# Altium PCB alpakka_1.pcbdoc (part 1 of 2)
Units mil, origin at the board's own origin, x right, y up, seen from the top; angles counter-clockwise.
Board outline 6704.54 x 4318.9 mil, 4 copper layers (Top Layer, Inner1, Inner2, Bottom Layer); 97 components, 87 nets, 400 pads, 319 vias.
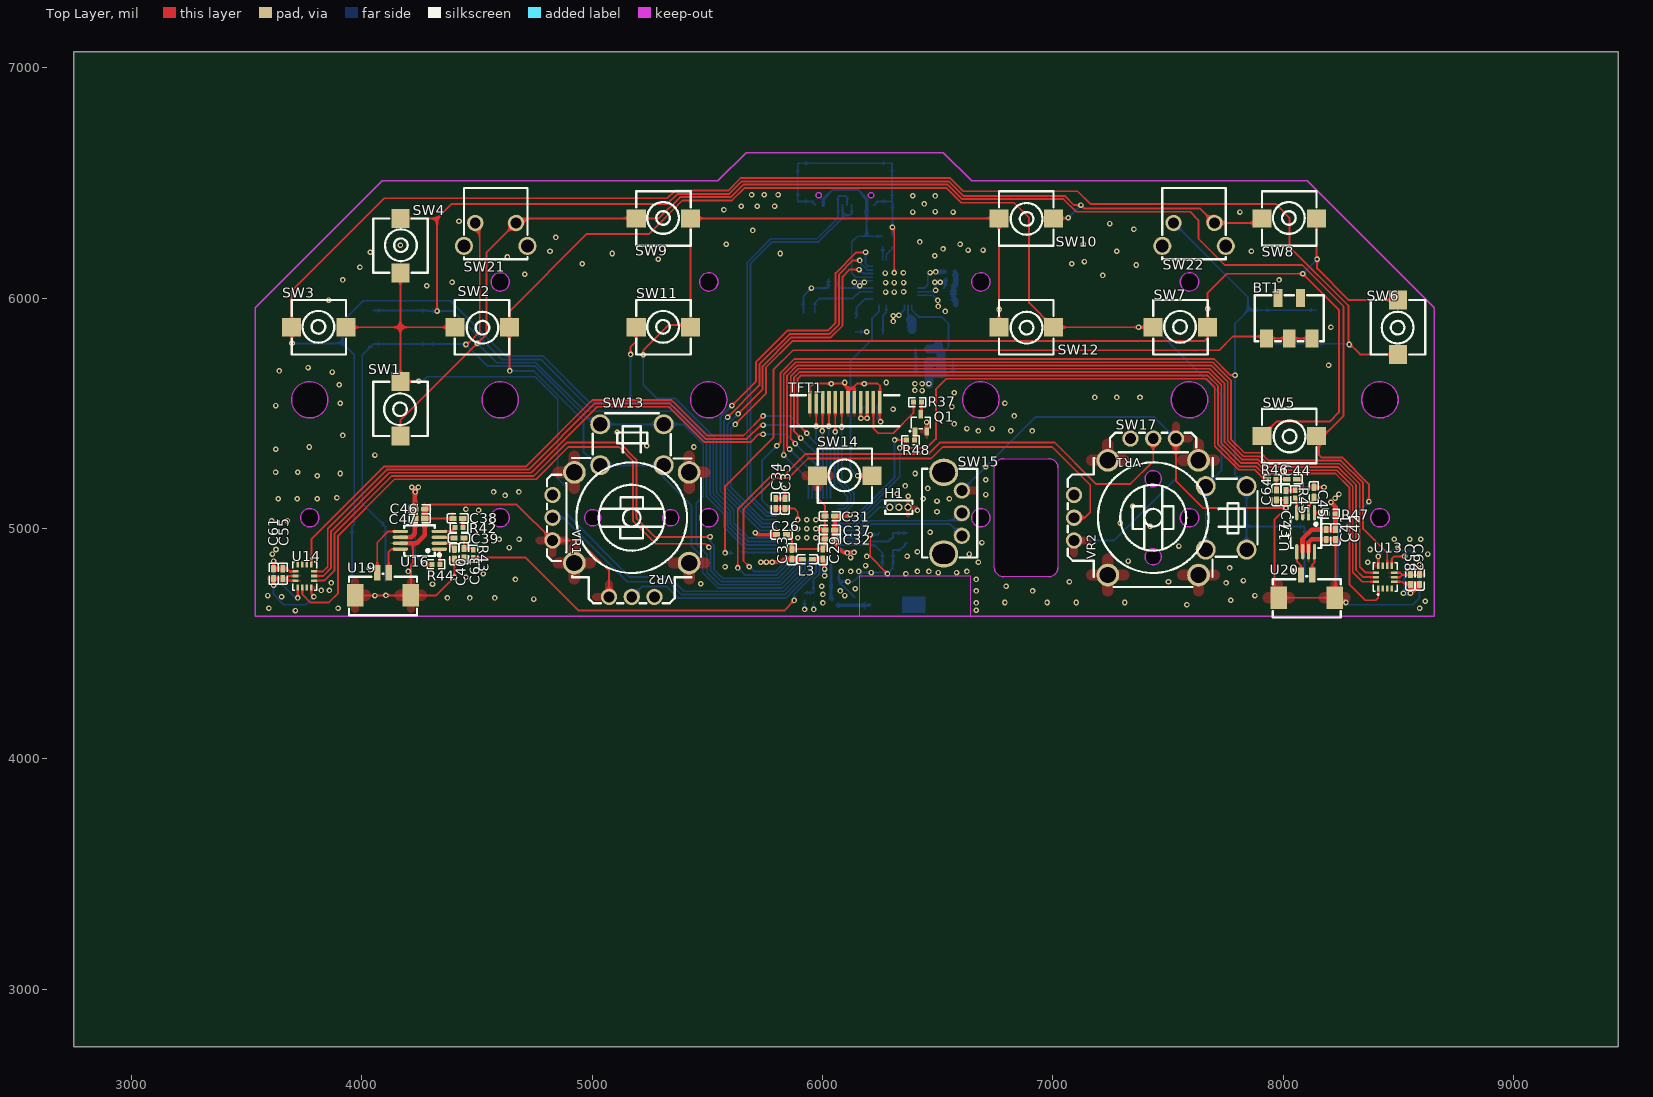
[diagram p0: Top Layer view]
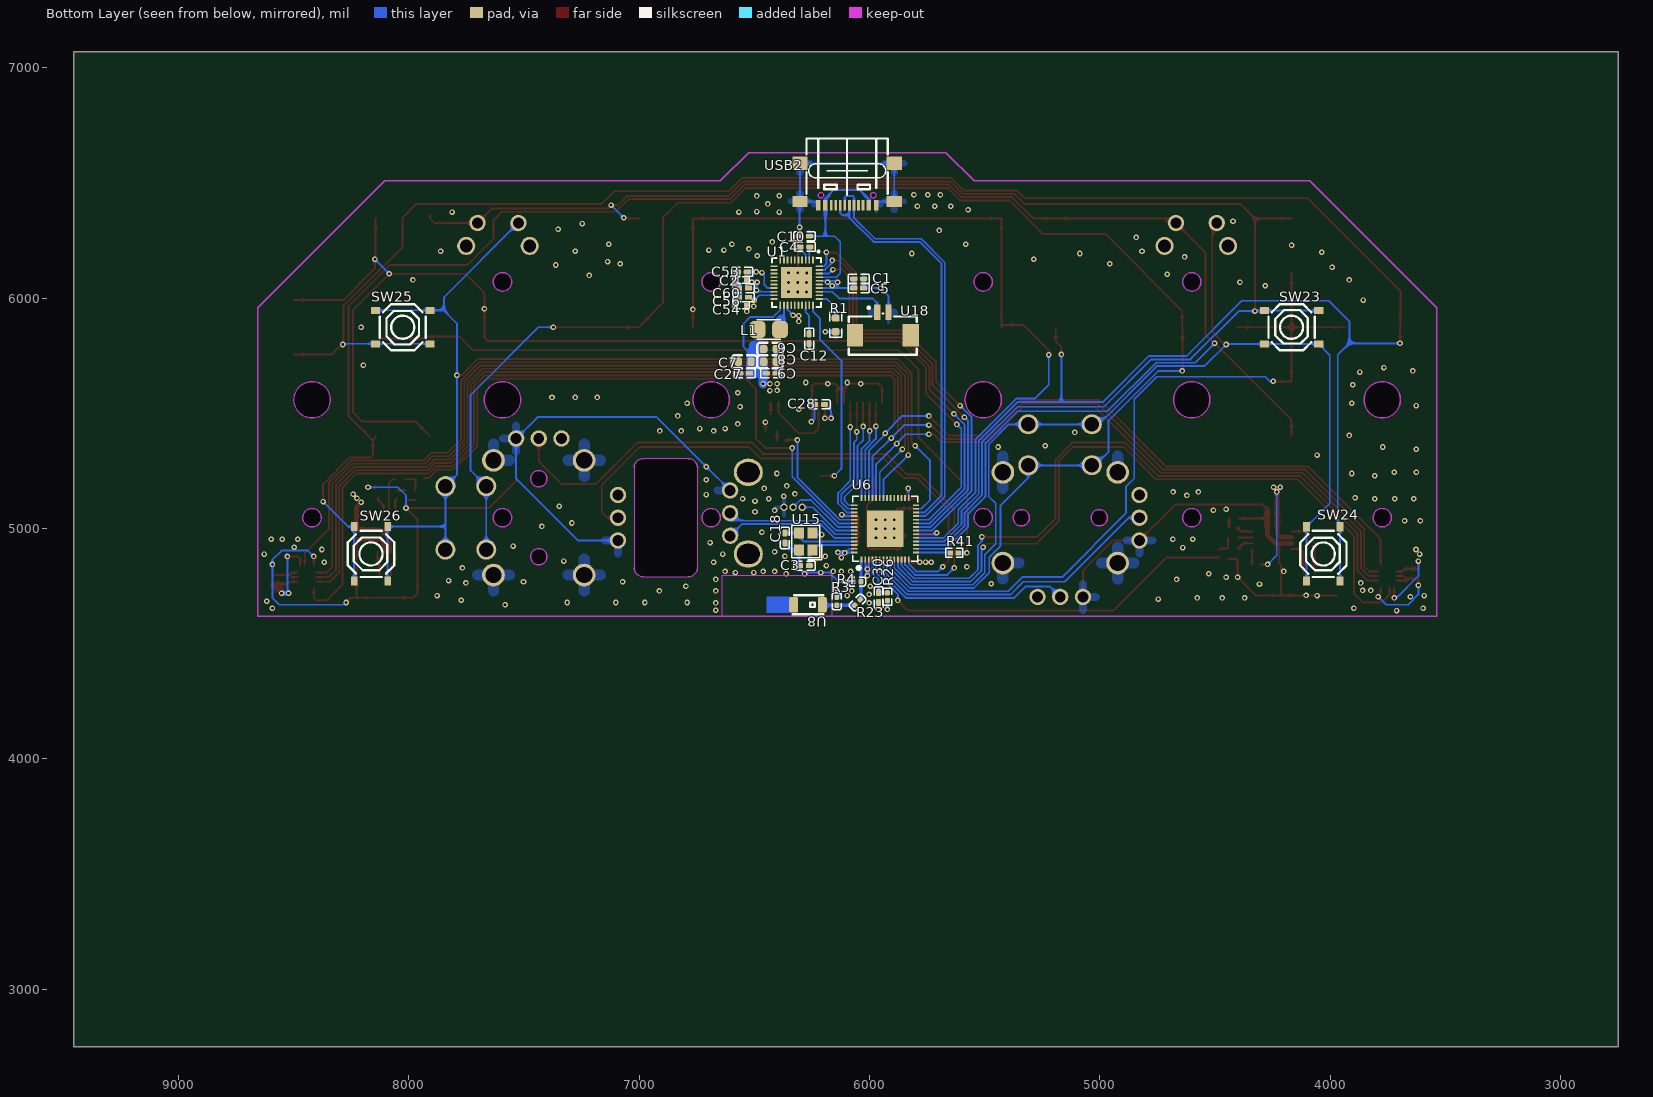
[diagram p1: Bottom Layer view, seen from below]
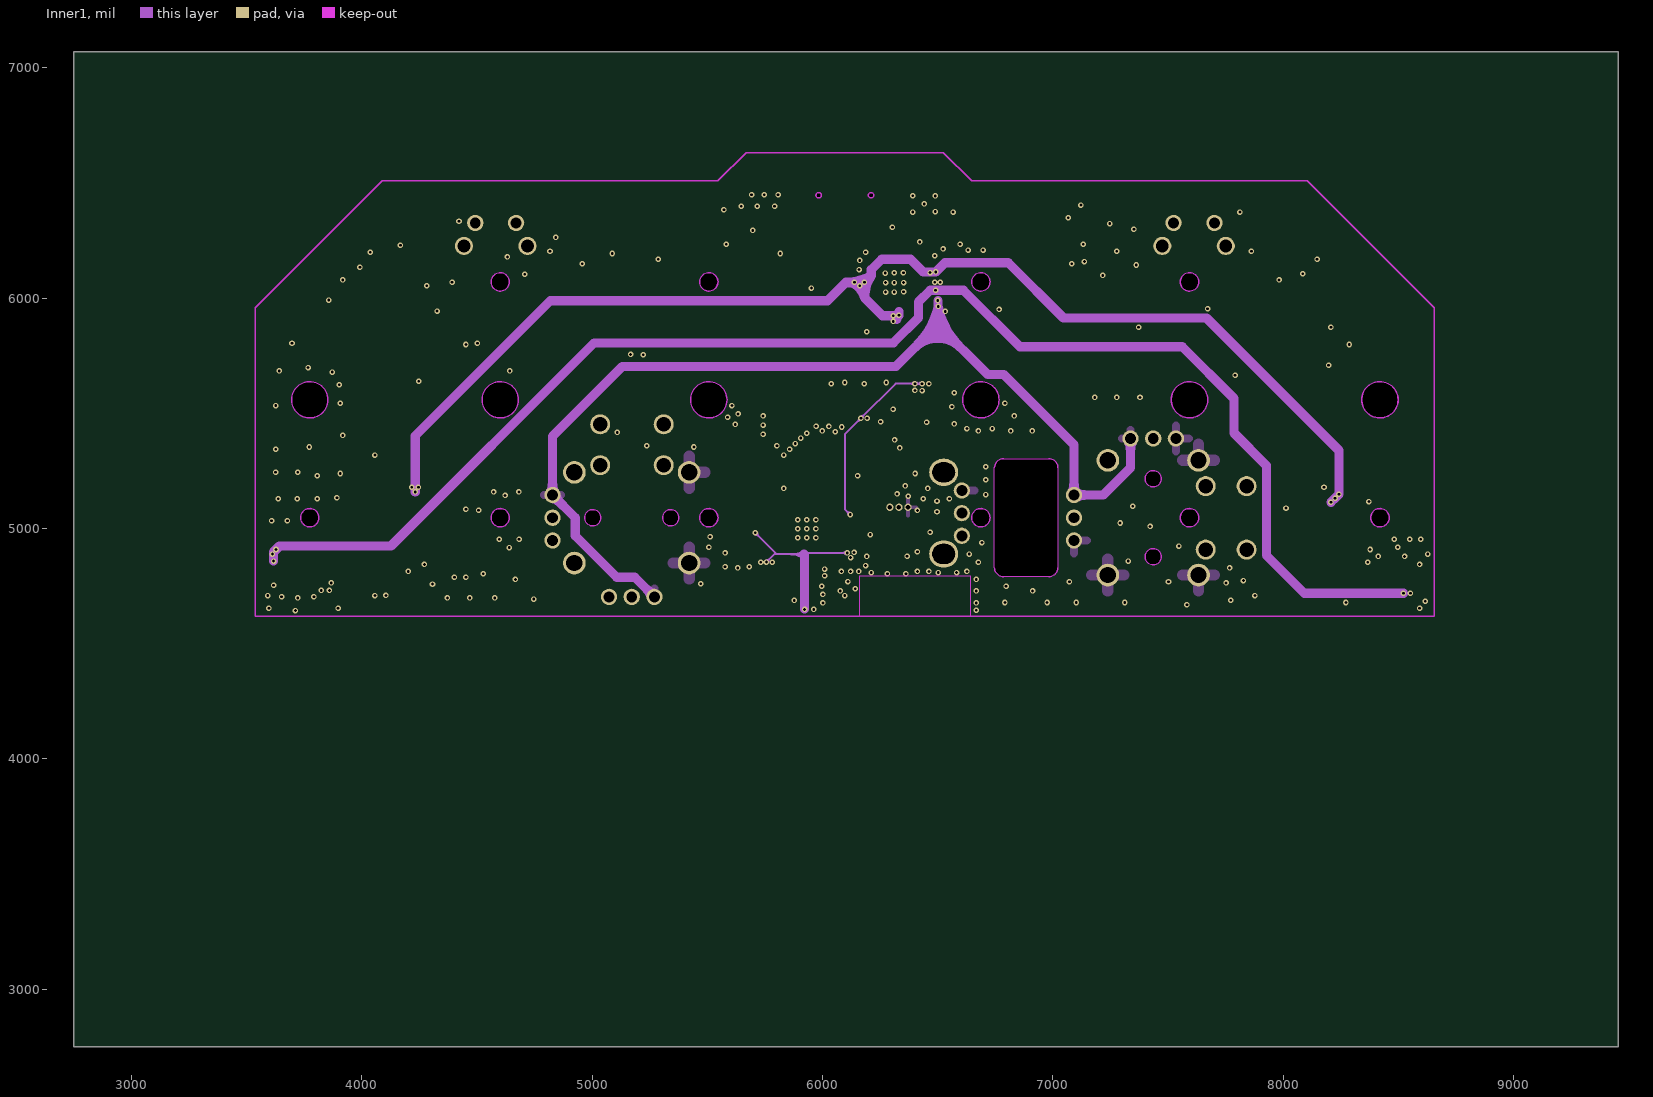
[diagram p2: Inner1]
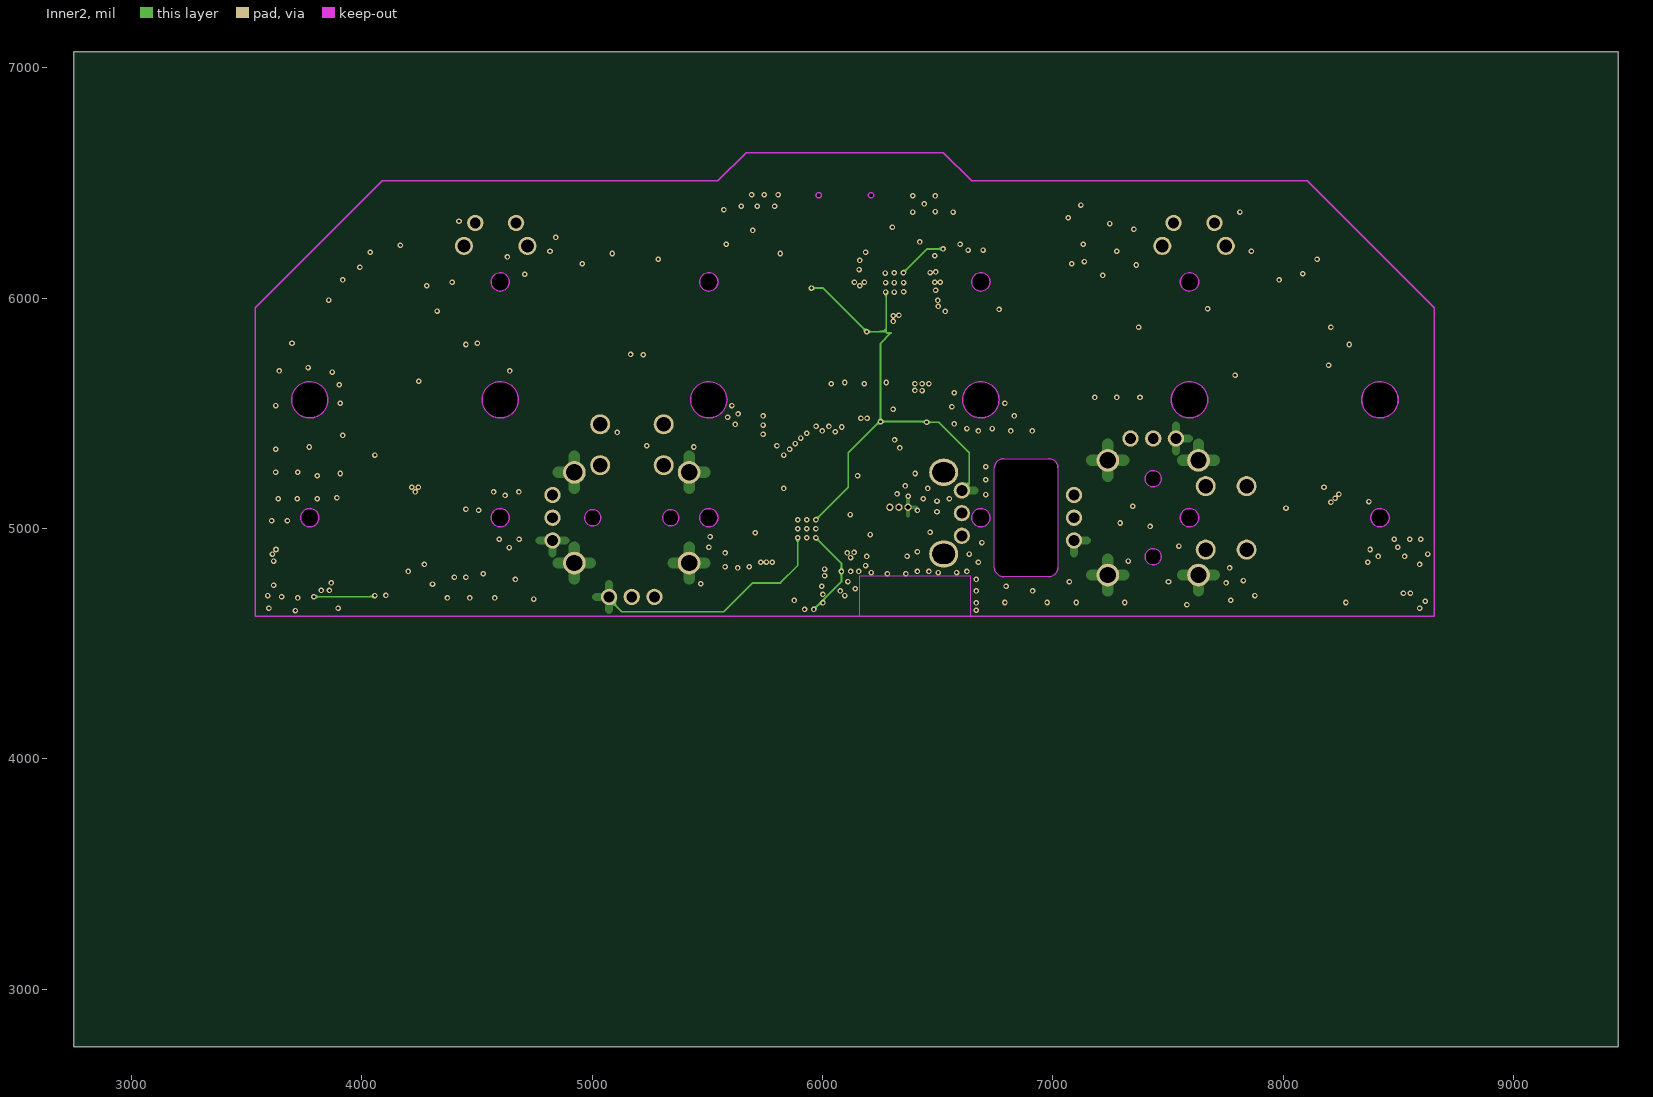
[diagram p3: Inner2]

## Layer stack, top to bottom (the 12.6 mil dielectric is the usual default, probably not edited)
Top Layer: signal copper (thickness not stored)
Dielectric: dielectric 12.6, FR-4, Dk 4.8
Inner1: signal copper (thickness not stored)
Dielectric: dielectric 12.6, FR-4, Dk 4.8
Inner2: signal copper (thickness not stored)
Dielectric: dielectric 12.6, FR-4, Dk 4.8
Bottom Layer: signal copper (thickness not stored)

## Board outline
9454.54,2750 2750,2750 2750,7068.9 9454.54,7068.9
cut-out: 3853.43,5558.11 cw(c3774.43,5558.11) 3695.43,5558.11 cw(c3774.43,5558.11)
cut-out: 3814.43,5046.3 cw(c3774.43,5046.3) 3734.43,5046.3 cw(c3774.43,5046.3)
cut-out: 4680.21,5558.11 cw(c4601.21,5558.11) 4522.21,5558.11 cw(c4601.21,5558.11)
cut-out: 5585.72,5558.11 cw(c5506.72,5558.11) 5427.72,5558.11 cw(c5506.72,5558.11)
cut-out: 6766.82,5558.11 cw(c6687.82,5558.11) 6608.82,5558.11 cw(c6687.82,5558.11)
cut-out: 7672.33,5558.11 cw(c7593.33,5558.11) 7514.33,5558.11 cw(c7593.33,5558.11)
cut-out: 8499.1,5558.11 cw(c8420.1,5558.11) 8341.1,5558.11 cw(c8420.1,5558.11)
cut-out: 4641.21,5046.3 cw(c4601.21,5046.3) 4561.21,5046.3 cw(c4601.21,5046.3)
cut-out: 4641.21,6069.92 cw(c4601.21,6069.92) 4561.21,6069.92 cw(c4601.21,6069.92)
cut-out: 5546.72,5046.3 cw(c5506.72,5046.3) 5466.72,5046.3 cw(c5506.72,5046.3)
cut-out: 5546.72,6069.92 cw(c5506.72,6069.92) 5466.72,6069.92 cw(c5506.72,6069.92)
cut-out: 6727.82,5046.3 cw(c6687.82,5046.3) 6647.82,5046.3 cw(c6687.82,5046.3)
cut-out: 6727.82,6069.92 cw(c6687.82,6069.92) 6647.82,6069.92 cw(c6687.82,6069.92)
cut-out: 8460.1,5046.3 cw(c8420.1,5046.3) 8380.1,5046.3 cw(c8420.1,5046.3)
cut-out: 7633.33,6069.92 cw(c7593.33,6069.92) 7553.33,6069.92 cw(c7593.33,6069.92)
cut-out: 7633.33,5046.3 cw(c7593.33,5046.3) 7553.33,5046.3 cw(c7593.33,5046.3)
cut-out: 6786.25,5302.14 6983.1,5302.27 cw(c6983.1,5262.91) 7022.47,5262.9 7022.47,4829.76 cw(c6982.82,4830.04) 6983.1,4790.39 6786.25,4790.39 cw(c6786.25,4829.76) 6746.88,4829.76 6746.88,5262.9 cw(c6786.25,5262.76)

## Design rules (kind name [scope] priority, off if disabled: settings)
BoardOutlineClearance safeClearance1 [All] p0: genericclearance=10 ignorepadtopadclearanceinfootprint=FALSE except(0: Arc-SplitContinuation Track-SplitContinuation SMDPad-SplitContinuation THPad-SplitContinuation Via-SplitContinuation Fill-SplitContinuation Poly-SplitContinuation Region-SplitContinuation Text-SplitContinuation; 6: Track-CutoutEdge SMDPad-CutoutEdge THPad-CutoutEdge Via-CutoutEdge Fill-CutoutEdge Region-CutoutEdge; 11.8: Track-OutlineEdge SMDPad-OutlineEdge THPad-OutlineEdge Via-OutlineEdge Fill-OutlineEdge Region-OutlineEdge Poly-OutlineEdge Text-OutlineEdge)
Clearance safeClearance1 [(InNet('GND') OR InNet('XTAL_P') OR InNet('XTAL_N') OR InNet('VDD3V3') OR InNet('$1N11781') OR InNet('ESP_EN') OR InNet('VDD_SPI') OR InNet('$1N13646') OR InNet('$1N13645') OR InNet('$1N11778') OR InNet('GPIO0') OR InNet('GPIO5') OR InNet('GPIO6') OR InNet('GPIO7') OR InNet('GPIO10') OR InNet('GPIO11') OR InNet('GPIO12') OR InNet('GPIO13') OR InNet('GPIO14') OR InNet('GPIO15') OR InNet('GPIO16') OR InNet('GPIO17') OR InNet('GPIO18') OR InNet('GPIO19') OR InNet('GPIO20') OR InNet('GPIO21') OR InNet('SPIHD') OR InNet('SPIWP') OR InNet('SPICS0') OR InNet('SPICLK') OR InNet('SPIQ') OR InNet('SPID') OR InNet('GPIO48') OR InNet('GPIO47') OR InNet('GPIO33') OR InNet('GPIO34') OR InNet('GPIO35') OR InNet('GPIO36') OR InNet('GPIO37') OR InNet('GPIO38') OR InNet('GPIO39') OR InNet('GPIO40') OR InNet('GPIO41') OR InNet('GPIO42') OR InNet('GPIO43') OR InNet('GPIO44') OR InNet('VBUS') OR InNet('$1N15366') OR InNet('$1N17243') OR InNet('EC-') OR InNet('EC+') OR InNet('$1N22693') OR InNet('$1N22623') OR InNet('$1N17767') OR InNet('$1N17771') OR InNet('$1N22969') OR InNet('$1N22964') OR InNet('$1N17778') OR InNet('$1N17783') OR InNet('$1N23525') OR InNet('$1N23526') OR InNet('$1N23528') OR InNet('$1N23542') OR InNet('$1N23545') OR InNet('$1N23523') OR InNet('$1N23530') OR InNet('VSYS') OR InNet('ALDO1') OR InNet('$1N24380') OR InNet('VRTC') OR InNet('$1N24407') OR InNet('TS') OR InNet('PMIC_PWROK') OR InNet('PMIC_PWRON') OR InNet('BAT') OR InNet('ALDO2') OR InNet('ALDO3') OR InNet('ALDO4') OR InNet('$1N27373') OR InNet('ADC1') OR InNet('ADC2') OR InNet('ADC3') OR InNet('ADC4') OR InNet('$1N36224') OR InNet('GPIO3') OR InNet('GPIO4') OR InNet('$1N52523'))] p1: gap=7 ignorepadtopadclearanceinfootprint=FALSE except(6: Track-Track Track-SMDPad SMDPad-SMDPad Track-THPad SMDPad-THPad THPad-THPad Track-Via SMDPad-Via THPad-Via Via-Via Track-Fill SMDPad-Fill THPad-Fill Via-Fill Fill-Fill Track-Region SMDPad-Region THPad-Region Via-Region Fill-Region Region-Region Track-Poly SMDPad-Poly THPad-Poly Via-Poly Fill-Poly Region-Poly Poly-Poly Track-Text SMDPad-Text THPad-Text Via-Text Fill-Text Region-Text Poly-Text Text-Text Track-Hole SMDPad-Hole THPad-Hole Via-Hole Fill-Hole Region-Hole Poly-Hole Text-Hole; 11.8: Track-Sheet SMDPad-Sheet THPad-Sheet Via-Sheet Fill-Sheet Region-Sheet Poly-Sheet Text-Sheet Sheet-Hole)
DiffPairsRouting differentialPair [All] p1: maxuncoupledlength=100 minlimit=6 maxlimit=6 mostfreqgap=6 toplayer_minwidth=5 toplayer_prefwidth=10 toplayer_maxwidth=100 bottomlayer_minwidth=5 bottomlayer_prefwidth=10 bottomlayer_maxwidth=100 midlayer1_minwidth=5 midlayer1_prefwidth=10 midlayer1_maxwidth=100 midlayer2_minwidth=5 midlayer2_prefwidth=10 midlayer2_maxwidth=100
PasteMaskExpansion Common [All] p1: expansion=0
PlaneConnect innerPlane [All] p1: planeconnectstyle=Relief reliefexpansion=20 reliefentries=4 reliefconductorwidth=10 reliefairgap=10
PolygonConnect CopperRegion [All] p1: connectstyle=Relief reliefentries=4 reliefconductorwidth=0 polygonreliefangle="90 Angle" airgapwidth=9.8
PolygonConnect CopperRegion1 [All] p1: connectstyle=Relief reliefentries=4 reliefconductorwidth=0 polygonreliefangle="90 Angle" airgapwidth=9.8
RoutingVias viaSize [All] p1: viastyle="Through Hole" holewidth=12 minholewidth=11.8 maxholewidth=236.2 width=24 minwidth=19.7 maxwidth=393.7
SolderMaskExpansion Common [All] p1: useseparateexpansions=TRUE expansion=0 expansionbottom=0
Width trackWidth [All] p1: maxlimit=100 minlimit=8 preferedwidth=10

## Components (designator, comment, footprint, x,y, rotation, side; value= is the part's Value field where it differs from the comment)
BT1 "BC-25-3P" CONN-SMD_BC-25-3P 8026.37,5912.43 r270 top
C1 "CL05A105KA5NQNC" C0402#1 6047.27,6083.23 r0 bottom
C2 "CL05A225MQ5NSNC" C0402#2 6557.27,6078.23 r180 bottom
C3 "0402CG220J500NT" C0402#1 6282.27,4838.23 r180 bottom
C4 "CL05A105KA5NQNC" C0402#1 6280.81,6221.77 r180 bottom
C5 "CL05A105KA5NQNC" C0402#1 6047.27,6043.23 r0 bottom
C6 "CL10A226MQ8NRNC" C0603 6432.27,5778.23 r0 bottom
C7 "CL10A226MQ8NRNC" C0603 6542.27,5723.23 r180 bottom
C8 "CL10A226MQ8NRNC" C0603 6432.27,5723.23 r0 bottom
C9 "CL05B104KO5NNNC" C0402#1 6427.27,5673.23 r0 bottom
C10 "CL05A106MQ5NUNC" C0402#1 6282.27,6268.23 r180 bottom
C12 "CL05A105KA5NQNC" C0402#1 6262.27,5823.23 r90 bottom
C18 "0402CG220J500NT" C0402#1 6367.27,4958.23 r270 bottom
C26 "CL05A106MQ5NUNC" C0402#3 5822.27,4973.23 r180 top
C27 "CL05A105KA5NQNC" C0402#1 6542.27,5673.23 r180 bottom
C28 "CL05B104KO5NNNC" C0402#1 6217.27,5538.23 r180 bottom
C29 "CL05B104KO5NNNC" C0402#3 6001.54,4888.85 r270 top
C30 "CL05B104KO5NNNC" C0402#1 5960.81,4699.69 r90 bottom
C31 "CL05B104KO5NNNC" C0402#3 6032.27,5053.23 r0 top
C32 "CL05A105KA5NQNC" C0402#3 6032.27,4953.23 r0 top
C33 "CL05B104KO5NNNC" C0402#3 5867.27,4888.23 r270 top
C34 "CL05B104KO5NNNC" C0402#3 5797.27,5108.23 r90 top
C35 "CL05A105KA5NQNC" C0402#3 5837.27,5108.23 r90 top
C37 "CL05B103KB5NNNC" C0402#4 6032.27,4993.23 r0 top
C38 "CL05B104KB54PNC" C0402#5 4417.27,5043.23 r0 top
C39 "CL05B104KB54PNC" C0402#5 4422.27,4958.23 r180 top
C40 "CL05A105KA5NQNC" C0402#3 4402.27,4888.23 r270 top
C41 "CL05A105KA5NQNC" C0402#3 8187.27,4973.23 r90 top
C42 "CL05B104KB54PNC" C0402#5 8227.27,4973.23 r90 top
C43 "CL05B104KB54PNC" C0402#5 8012.27,5143.23 r90 top
C44 "CL05B104KB54PNC" C0402#5 8037.27,5213.23 r0 top
C45 "CL05A105KA5NQNC" C0402#3 8133.73,5156.77 r90 top
C46 "CL05A105KA5NQNC" C0402#3 4252.27,5083.23 r180 top
C47 "CL05B104KB54PNC" C0402#5 4252.27,5043.23 r180 top
C53 "CL05A105KA5NQNC" C0402#1 6552.27,6113.23 r180 bottom
C54 "CL05A225MQ5NSNC" C0402#2 6557.27,5968.23 r180 bottom
C55 "CL05B104KB54PNC" C0402#5 3657.27,4803.23 r90 top
C56 "CL05B104KB54PNC" C0402#5 6547.27,6003.23 r180 bottom
C58 "CL05B104KB54PNC" C0402#5 8552.27,4778.23 r270 top
C60 "CL05B104KB54PNC" C0402#5 6547.27,6043.23 r180 bottom
C61 "CL05A105KA5NQNC" C0402#3 3617.27,4803.23 r90 top
C62 "CL05A105KA5NQNC" C0402#3 8592.27,4778.23 r270 top
C63 "CL05B104KB54PNC" C0402#5 4443.73,4891.77 r90 top
C64 "CL05B104KB54PNC" C0402#5 7970.81,5144.69 r90 top
H1 "ZX-PZ1.0-1-3PZZ" HDR-TH_3P-P1.00-V-M-3 6332.09,5091.65 r0 top
L1 "WPN252012H1R0MT" IND-SMD_L2.5-W2.0_WPN252012H 6437.27,5863.23 r180 bottom
L3 "LQG15HS2N0S02D" L0402 5934.67,4865.7 r0 top
Q1 "HXY2102EI" SOT-323-3_L2.1-W1.3-P1.30-LS2.3-BR 6427.27,5458.23 r270 top
R1 "NCP18XH103F03RB" R0603 6147.27,5883.23 r270 bottom
R3 "0402WGF0000TCE" R0402#1 6142.27,4683.23 r270 bottom
R4 "0402WGF0000TCE" R0402#1 6054.34,4769.06 r180 bottom
R23 "0402WGF0000TCE" R0402#1 6052.27,4678.23 r135 bottom
R26 "0402WGF1002TCE" R0402#1 5922.27,4703.23 r270 bottom
R37 "AF0402FR-0720RL" R0402#2 6412.27,5548.23 r180 top
R41 "0402WGF5100TCE" R0402#2 5632.27,4893.23 r0 bottom
R42 "0402WGF3002TCE" R0402#2 4422.27,5003.23 r180 top
R43 "0402WGF3002TCE" R0402#2 4484.31,4890.27 r90 top
R44 "0402WGF1002TCE" R0402#3 4322.27,4843.23 r0 top
R45 "0402WGF3002TCE" R0402#2 8052.27,5148.23 r270 top
R46 "0402WGF3002TCE" R0402#2 7952.27,5213.23 r0 top
R47 "0402WGF1002TCE" R0402#3 8207.27,5063.23 r180 top
R48 "0402WGF1002TCE" R0402#3 6382.27,5383.23 r0 top
SW1 "SKPMAME010" KEY-SMD_2P-L6.0-W6.0-P6.00 4168.16,5518.76 r90 top
SW2 "SKPMAME010" KEY-SMD_2P-L6.0-W6.0-P6.00 4522.46,5873.06 r180 top
SW3 "SKPMAME010" KEY-SMD_2P-L6.0-W6.0-P6.00 3813.76,5873.06 r0 top locked
SW4 "SKPMAME010" KEY-SMD_2P-L6.0-W6.0-P6.00 4168.16,6227.36 r270 top
SW5 "SKPMAME010" KEY-SMD_2P-L6.0-W6.0-P6.00 8026.36,5400.66 r180 top locked
SW6 "SKPMAME010" KEY-SMD_2P-L6.0-W6.0-P6.00 8498.86,5873.06 r90 top locked
SW7 "SKPMAME010" KEY-SMD_2P-L6.0-W6.0-P6.00 7553.96,5873.06 r0 top locked
SW8 "SKPMAME010" KEY-SMD_2P-L6.0-W6.0-P6.00 8026.36,6345.56 r0 top
SW9 "SKPMAME010" KEY-SMD_2P-L6.0-W6.0-P6.00 5309.86,6345.56 r0 top
SW10 "SKPMAME010" KEY-SMD_2P-L6.0-W6.0-P6.00 6884.66,6345.56 r180 top
SW11 "SKPMAME010" KEY-SMD_2P-L6.0-W6.0-P6.00 5309.86,5873.06 r0 top
SW12 "SKPMAME010" KEY-SMD_2P-L6.0-W6.0-P6.00 6884.66,5873.06 r180 top
SW13 "RKJXV1224005" SW-TH_RKJXV1224005#1 5124.76,5077.06 r180 top locked
SW14 "SKPMAME010" KEY-SMD_2P-L6.0-W6.0-P6.00 6097.27,5228.23 r0 top
SW15 "EC10E1220503" SW-TH_EC10EXXXXXXX 6565.79,5066.03 r90 top
SW17 "RKJXV1224005" SW-TH_RKJXV1224005#2 7466.56,5093.66 r90 top
SW21 "SKHHLNA010" KEY-TH_SKHHLNA010 4581.54,6275.86 r180 top
SW22 "SKHHLNA010" KEY-TH_SKHHLNA010 7613.04,6275.86 r180 top
SW23 "TS-1187A-B-A-B" SW-SMD_4P-L5.1-W5.1-P3.70-LS6.5-TL_H1.5 4168.16,5873.06 r0 bottom
SW24 "TS-1187A-B-A-B" SW-SMD_4P-L5.1-W5.1-P3.70-LS6.5-TL_H1.5 4030.36,4888.86 r270 bottom
SW25 "TS-1187A-B-A-B" SW-SMD_4P-L5.1-W5.1-P3.70-LS6.5-TL_H1.5 8026.4,5873.07 r180 bottom locked
SW26 "TS-1187A-B-A-B" SW-SMD_4P-L5.1-W5.1-P3.70-LS6.5-TL_H1.5 8164.2,4889.06 r270 bottom
TFT1 "0.71园tft" 0.71圆tft 6097.27,5728.23 r0 top
U1 "AXP2101" QFN-40_L5.0-W5.0-P0.40-TL-EP3.4 6316.57,6066.79 r270 bottom
U6 "ESP32-S3" QFN-56_L7.0-W7.0-P0.40-TL-EP4.0 5932.27,4998.23 r90 bottom
U8 "ANT3216LL00R2400A" ANT-SMD_L3.2-W1.6 6267.27,4668.23 r0 bottom
U13 "ICM-42688-P" LGA-14_L3.0-W2.5-P0.50-TL 8442.27,4788.23 r90 top
U14 "ICM-42688-P" LGA-14_L3.0-W2.5-P0.50-TL 3752.27,4793.23 r270 top
U15 "X252040MMB4SI" CRYSTAL-SMD_4P-L2.5-W2.0-BL 6277.27,4943.23 r90 bottom
U16 "NS4150B_C189961" MSOP-8_L3.0-W3.0-P0.65-LS5.0-BL 4252.27,4948.23 r90 top
U17 "NS4150B_C189961" MSOP-8_L3.0-W3.0-P0.65-LS5.0-BL 8097.27,4983.23 r180 top
U18 "WAFER-MX1.25-2PWB" CONN-SMD_2P-P1.25_XUNPU_WAFER-MX1.25-2PWB 5942.27,5888.23 r180 bottom
U19 "WAFER-MX1.25-2PWB" CONN-SMD_2P-P1.25_XUNPU_WAFER-MX1.25-2PWB 4092.27,4758.23 r0 top
U20 "WAFER-MX1.25-2PWB" CONN-SMD_2P-P1.25_XUNPU_WAFER-MX1.25-2PWB 8102.27,4748.23 r0 top
USB2 "TYPE-C 16P QTWT" USB-TYPE-C-SMD_TYPE-C-16P-QTWT 6097.27,6494.06 r0 bottom locked

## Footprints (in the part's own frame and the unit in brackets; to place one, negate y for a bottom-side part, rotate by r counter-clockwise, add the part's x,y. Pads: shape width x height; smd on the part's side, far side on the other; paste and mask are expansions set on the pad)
0.71圆tft [mm]
  rect 0.392x2.5 smd: 1(3.85,-4.606) 2(3.15,-4.606) 3(2.45,-4.606) 4(1.75,-4.606) 5(1.05,-4.606) 6(0.35,-4.606) 7(-0.35,-4.606) 8(-1.05,-4.606) 9(-1.75,-4.606) 10(-2.45,-4.606) 11(-3.15,-4.606) 12(-3.85,-4.606)
  silkscreen extent -5.97,-7.24 6.03,-3.81
ANT-SMD_L3.2-W1.6 [mil]
  rrect50% 39.4x68.9 smd: 1(-62.1,0) 2(62.1,0)
  Top Layer region: 80,-35.87 178.43,-35.87 178.43,35 80,35
  silkscreen extent -66,-41 66,42
C0402#1 [mm]
  rrect50% 0.79x0.54 smd: 1(-0.545,0) 2(0.545,0)
  silkscreen extent -1.17,-0.5 1.17,0.5
C0402#2 [mm]
  rrect50% 0.508x0.54 smd: 1(-0.545,0) 2(0.545,0)
  silkscreen extent -0.91,-0.37 0.91,0.37
C0402#3 [mm]
  rrect30% 0.79x0.54 smd: 1(-0.545,0) 2(0.545,0)
  silkscreen extent -1.17,-0.5 1.17,0.5
C0402#4 [mm]
  rrect20% 0.79x0.54 smd: 1(-0.545,0) 2(0.545,0)
  silkscreen extent -1.17,-0.5 1.17,0.5
C0402#5 [mm]
  rect 0.79x0.54 smd: 1(-0.545,0) 2(0.545,0)
  silkscreen extent -1.17,-0.5 1.17,0.5
C0603 [mm]
  rrect50% 0.8x0.9 smd: 1(-0.7,0) 2(0.7,0)
  silkscreen extent -1.41,-0.71 1.39,0.72
CONN-SMD_2P-P1.25_XUNPU_WAFER-MX1.25-2PWB [mm]
  rect 0.7x1.7 smd: 1(-0.625,1.25) 2(0.625,1.25)
  rect 1.8x2.5 smd: 3(3.075,-1.25) 4(-3.075,-1.25)
  silkscreen extent -3.75,-3.43 3.75,1.88
CONN-SMD_BC-25-3P [mm]
  rect 2x1.4 smd: 1(2.225,2.5) 2(2.225,0) 3(2.225,-2.5)
  rect 2x1 smd: 4(-2.225,1.25) 5(-2.225,-1.25)
  silkscreen extent -2.54,-3.81 2.54,3.81
CRYSTAL-SMD_4P-L2.5-W2.0-BL [mm]
  rect 1.2x1.1 smd: 1(-0.95,-0.75) 2(0.95,-0.75) 3(0.95,0.75) 4(-0.95,0.75)
  silkscreen extent -2.01,-1.76 1.78,1.53
HDR-TH_3P-P1.00-V-M-3 [mm]
  round 0.8 hole 0.5: 1(-1,0) 2(0,0) 3(1,0)
  silkscreen extent -1.5,-0.75 1.5,0.75
IND-SMD_L2.5-W2.0_WPN252012H [mm]
  rrect50% 1.724x1.87 smd: 1(1.228,0) 2(-1.228,0)
  silkscreen extent -1.33,-1.09 1.33,1.09
KEY-SMD_2P-L6.0-W6.0-P6.00 [mm]
  rect 2.1x2 smd: 1(-3,0) 2(3,0)
  silkscreen extent -3,-3 3,3
KEY-TH_SKHHLNA010 [mm]
  round 1.8 hole 1.2: 1(-2.25,-1.27) 2(2.25,-1.27)
  round 2 hole 1.4: 3(3.5,1.27) 4(-3.5,1.27)
  silkscreen extent -3.5,-5.12 3.5,2.73
L0402 [mm]
  rrect50% 0.79x0.54 smd: 1(-0.545,0) 2(0.545,0)
  silkscreen extent -1.17,-0.5 1.17,0.5
LGA-14_L3.0-W2.5-P0.50-TL [mm]
  rect 0.675x0.28 smd: 1(-1.262,0.75) 2(-1.262,0.25) 3(-1.262,-0.25) 4(-1.262,-0.75) 8(1.262,-0.75) 9(1.262,-0.25) 10(1.262,0.25) 11(1.262,0.75)
  rect 0.28x0.675 smd: 5(-0.5,-1.012) 6(0,-1.012) 7(0.5,-1.012) 12(0.5,1.012) 13(0,1.012) 14(-0.5,1.012)
  silkscreen extent -1.98,-1.33 1.58,1.33
MSOP-8_L3.0-W3.0-P0.65-LS5.0-BL [mil]
  oval 14.33x66.61 smd: 1(-38.39,-84.49) 2(-12.79,-84.49) 3(12.8,-84.49) 4(38.39,-84.49) 5(38.39,84.49) 6(12.8,84.49) 7(-12.79,84.49) 8(-38.39,84.49)
  silkscreen extent -69,-90 65,68
QFN-40_L5.0-W5.0-P0.40-TL-EP3.4 [mil]
  oval 31.5x7.9 smd: 1(-98.4,70.9) 2(-98.4,55.1) 3(-98.4,39.4) 4(-98.4,23.6) 5(-98.4,7.9) 6(-98.4,-7.9) 7(-98.4,-23.6) 8(-98.4,-39.4) 9(-98.4,-55.1) 10(-98.4,-70.9) 21(98.4,-70.9) 22(98.4,-55.1) 23(98.4,-39.4) 24(98.4,-23.6) 25(98.4,-7.9) 26(98.4,7.9) 27(98.4,23.6) 28(98.4,39.4) 29(98.4,55.1) 30(98.4,70.9)
  oval 7.9x31.5 smd: 11(-70.9,-98.4) 12(-55.1,-98.4) 13(-39.4,-98.4) 14(-23.6,-98.4) 15(-7.9,-98.4) 16(7.9,-98.4) 17(23.6,-98.4) 18(39.4,-98.4) 19(55.1,-98.4) 20(70.9,-98.4) 31(70.9,98.4) 32(55.1,98.4) 33(39.4,98.4) 34(23.6,98.4) 35(7.9,98.4) 36(-7.9,98.4) 37(-23.6,98.4) 38(-39.4,98.4) 39(-55.1,98.4) 40(-70.9,98.4)
  rect 133.9x133.9 smd: 41(0,0)
  silkscreen extent -143,-106 106,106
QFN-56_L7.0-W7.0-P0.40-TL-EP4.0 [mm]
  rect 0.665x0.2 smd: 1(-3.408,2.6) 2(-3.408,2.2) 3(-3.408,1.8) 4(-3.408,1.4) 5(-3.408,1) 6(-3.408,0.6) 7(-3.408,0.2) 8(-3.408,-0.2) 9(-3.408,-0.6) 10(-3.408,-1) 11(-3.408,-1.4) 12(-3.408,-1.8) 13(-3.408,-2.2) 14(-3.408,-2.6) 29(3.408,-2.6) 30(3.408,-2.2) 31(3.408,-1.8) 32(3.408,-1.4) 33(3.408,-1) 34(3.408,-0.6) 35(3.408,-0.2) 36(3.408,0.2) 37(3.408,0.6) 38(3.408,1) 39(3.408,1.4) 40(3.408,1.8) 41(3.408,2.2) 42(3.408,2.6)
  rect 0.2x0.665 smd: 15(-2.6,-3.408) 16(-2.2,-3.408) 17(-1.8,-3.408) 18(-1.4,-3.408) 19(-1,-3.408) 20(-0.6,-3.408) 21(-0.2,-3.408) 22(0.2,-3.408) 23(0.6,-3.408) 24(1,-3.408) 25(1.4,-3.408) 26(1.8,-3.408) 27(2.2,-3.408) 28(2.6,-3.408) 43(2.6,3.408) 44(2.2,3.408) 45(1.8,3.408) 46(1.4,3.408) 47(1,3.408) 48(0.6,3.408) 49(0.2,3.408) 50(-0.2,3.408) 51(-0.6,3.408) 52(-1,3.408) 53(-1.4,3.408) 54(-1.8,3.408) 55(-2.2,3.408) 56(-2.6,3.408)
  rect 4x4 smd: 57(0,0)
  silkscreen extent -4.64,-3.58 3.58,3.58
R0402#1 [mm]
  rrect50% 0.566x0.54 smd: 1(-0.433,0) 2(0.433,0)
  silkscreen extent -0.94,-0.5 0.94,0.5
R0402#2 [mm]
  rect 0.566x0.54 smd: 1(-0.433,0) 2(0.433,0)
  silkscreen extent -0.94,-0.5 0.94,0.5
R0402#3 [mm]
  rrect20% 0.566x0.54 smd: 1(-0.433,0) 2(0.433,0)
  silkscreen extent -0.94,-0.5 0.94,0.5
R0603 [mil]
  rrect50% 31.75x34.02 smd: 1(-29.66,0) 2(29.66,0)
  silkscreen extent -55,-26 55,26
SOT-323-3_L2.1-W1.3-P1.30-LS2.3-BR [mm]
  rect 0.919x0.525 smd: 1(0.95,-0.65) 2(0.95,0.65) 3(-0.95,0)
  silkscreen extent -0.62,-1.27 0.99,1.06
SW-SMD_4P-L5.1-W5.1-P3.70-LS6.5-TL_H1.5 [mm]
  rect 1x0.75 smd: 1(-3,1.85) 2(3,1.85) 3(-3,-1.85) 4(3,-1.85)
  silkscreen extent -2.55,-2.55 2.55,2.55
SW-TH_EC10EXXXXXXX [mm]
  oval 3x3.2 hole 2.2 slot 2.5 at 90 deg: 4(-4.5,1) 5(4.5,1)
  round 1.8 hole 1.2: A(-2.5,-1) B(0,-1) C(2.5,-1)
  silkscreen extent -4.9,-2.7 4.9,3.4
SW-TH_RKJXV1224005#1 [mm]
  round 1.8 hole 1.2: 1(7.527,-1.719) 2(7.527,0.781) 3(7.527,3.281) 4(1.297,9.511) 5(-1.202,9.511) 6(-3.703,9.511)
  round 2.5 hole 1.8: 7(-7.527,5.781) 8(-7.527,-4.219) 9(5.123,-4.219) 10(5.123,5.781)
  round 2.2 hole 1.6: a(-4.722,-5.011) b(-4.722,-9.511) c(2.278,-5.011) d(2.278,-9.511)
  Board Outline Layer circle w0.005: c-5.503,0.781 r0.9
  Board Outline Layer circle w0.005: c3.097,0.781 r0.9
  Board Outline Layer region: -6.403,0.781 -6.314,1.171 -6.064,1.485 -5.703,1.658 -5.302,1.658 -4.942,1.485 -4.692,1.171 -4.603,0.781 -4.603,0.781 -4.692,0.39 -4.942,0.077 -5.302,-0.097 -5.703,-0.097 -6.064,0.077 -6.314,0.39 -6.403,0.781
  Board Outline Layer region: 2.197,0.781 2.286,1.171 2.536,1.485 2.897,1.658 3.298,1.658 3.658,1.485 3.908,1.171 3.997,0.781 3.997,0.781 3.908,0.39 3.658,0.077 3.298,-0.097 2.897,-0.097 2.536,0.077 2.286,0.39 2.197,0.781
  Multi-Layer board cut-out: -6.403,0.781 -6.314,1.171 -6.064,1.485 -5.703,1.658 -5.302,1.658 -4.942,1.485 -4.692,1.171 -4.603,0.781 -4.603,0.781 -4.692,0.39 -4.942,0.077 -5.302,-0.097 -5.703,-0.097 -6.064,0.077 -6.314,0.39 -6.403,0.781
  Multi-Layer board cut-out: 2.197,0.781 2.286,1.171 2.536,1.485 2.897,1.658 3.298,1.658 3.658,1.485 3.908,1.171 3.997,0.781 3.997,0.781 3.908,0.39 3.658,0.077 3.298,-0.097 2.897,-0.097 2.536,0.077 2.286,0.39 2.197,0.781
  silkscreen extent -8.85,-10.72 8.15,10.2
SW-TH_RKJXV1224005#2 [mm]
  round 1.8 hole 1.2: 1(7.527,-1.719) 2(7.527,0.781) 3(7.527,3.281) 4(1.297,9.511) 5(-1.202,9.511) 6(-3.703,9.511)
  round 2.5 hole 1.8: 7(-7.527,5.781) 8(-7.527,-4.219) 9(5.123,-4.219) 10(5.123,5.781)
  round 2.2 hole 1.6: a(-4.722,-5.011) b(-4.722,-9.511) c(2.278,-5.011) d(2.278,-9.511)
  Board Outline Layer circle w0.005: c-5.503,0.781 r0.9
  Board Outline Layer circle w0.005: c3.097,0.781 r0.9
  Board Outline Layer region: -5.503,-0.119 -5.893,-0.03 -6.206,0.22 -6.38,0.581 -6.38,0.981 -6.206,1.342 -5.893,1.592 -5.503,1.681 -5.503,1.681 -5.112,1.592 -4.799,1.342 -4.625,0.981 -4.625,0.581 -4.799,0.22 -5.112,-0.03 -5.503,-0.119
  Board Outline Layer region: 3.097,-0.119 2.707,-0.03 2.394,0.22 2.22,0.581 2.22,0.981 2.394,1.342 2.707,1.592 3.097,1.681 3.097,1.681 3.488,1.592 3.801,1.342 3.975,0.981 3.975,0.581 3.801,0.22 3.488,-0.03 3.097,-0.119
  Multi-Layer board cut-out: -5.503,-0.119 -5.893,-0.03 -6.206,0.22 -6.38,0.581 -6.38,0.981 -6.206,1.342 -5.893,1.592 -5.503,1.681 -5.503,1.681 -5.112,1.592 -4.799,1.342 -4.625,0.981 -4.625,0.581 -4.799,0.22 -5.112,-0.03 -5.503,-0.119
  Multi-Layer board cut-out: 3.097,-0.119 2.707,-0.03 2.394,0.22 2.22,0.581 2.22,0.981 2.394,1.342 2.707,1.592 3.097,1.681 3.097,1.681 3.488,1.592 3.801,1.342 3.975,0.981 3.975,0.581 3.801,0.22 3.488,-0.03 3.097,-0.119
  silkscreen extent -8.85,-10.72 8.15,10.2
USB-TYPE-C-SMD_TYPE-C-16P-QTWT [mm]
  rect 1.7x1.5 smd: 0(-5.2,-2.309) 0(5.2,-2.309)
  rect 1.7x1.2 smd: 0(-5.2,1.891) 0(5.2,1.891)
  rect 0.5x1.14 smd: A1(-3.2,2.308) A4(-2.4,2.308) A9(2.4,2.308) A12(3.2,2.308)
  rect 0.3x1.14 smd: A5(-1.25,2.308) A6(-0.25,2.308) A7(0.25,2.308) A8(1.25,2.309) B5(1.75,2.308) B6(0.75,2.308) B7(-0.75,2.308) B8(-1.75,2.309)
  Board Outline Layer circle w0.005: c2.89,1.221 r0.3
  Board Outline Layer circle w0.005: c-2.89,1.221 r0.3
  Board Outline Layer region: 3.19,1.221 3.16,1.351 3.077,1.456 2.957,1.513 2.823,1.513 2.703,1.456 2.62,1.351 2.59,1.221 2.59,1.221 2.62,1.091 2.703,0.986 2.823,0.929 2.957,0.929 3.077,0.986 3.16,1.091 3.19,1.221
  Board Outline Layer region: -2.59,1.221 -2.62,1.351 -2.703,1.456 -2.823,1.513 -2.957,1.513 -3.077,1.456 -3.16,1.351 -3.19,1.221 -3.19,1.221 -3.16,1.091 -3.077,0.986 -2.957,0.929 -2.823,0.929 -2.703,0.986 -2.62,1.091 -2.59,1.221
  Multi-Layer board cut-out: 3.19,1.221 3.16,1.351 3.077,1.456 2.957,1.513 2.823,1.513 2.703,1.456 2.62,1.351 2.59,1.221 2.59,1.221 2.62,1.091 2.703,0.986 2.823,0.929 2.957,0.929 3.077,0.986 3.16,1.091 3.19,1.221
  Multi-Layer board cut-out: -2.59,1.221 -2.62,1.351 -2.703,1.456 -2.823,1.513 -2.957,1.513 -3.077,1.456 -3.16,1.351 -3.19,1.221 -3.19,1.221 -3.16,1.091 -3.077,0.986 -2.957,0.929 -2.823,0.929 -2.703,0.986 -2.62,1.091 -2.59,1.221
  silkscreen extent -4.46,-5.05 4.48,1.2

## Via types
v1: diameter 24.02, hole 12.01, Top Layer to Bottom Layer, 310 vias
v2: diameter 24, hole 12, Top Layer to Bottom Layer, 9 vias

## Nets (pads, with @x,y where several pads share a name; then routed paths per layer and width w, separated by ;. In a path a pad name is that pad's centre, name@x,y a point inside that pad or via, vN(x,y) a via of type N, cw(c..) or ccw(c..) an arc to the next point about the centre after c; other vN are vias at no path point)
$1N11778: R4.2 R23.2 U6.1 | length 173.5
  Bottom Layer w13.75: R4.2@6037.3,4769.06 U6.1@6037.3,4862.56
  Bottom Layer w13.8: R4.2@6037.3,4769.06 6037.3,4693.2 R23.2@6040.22,4690.28
$1N11781: C29.2 L3.2 U6.2 U6.3 | length 210.5
  Top Layer w15: L3.2@5956.13,4865.7 5957.81,4867.39 C29.2@6001.54,4867.39 6009.4,4859.53 v1(6009.4,4823.23)
  Bottom Layer w8: U6.3@6003.13,4864.07 6003.13,4829.5 v1(6009.4,4823.23) 6018.88,4832.71 U6.2@6018.88,4864.07
  Bottom Layer w20: v1(6009.4,4794.5) v1(6009.4,4823.23)
$1N13645: Q1.3 R37.1 | length 53.4
  Top Layer w8: Q1.3@6427.27,5495.63 6429.31,5497.67 R37.1@6429.31,5548.23
$1N13646: R37.2 TFT1.2 | length 378.8
  Top Layer w8: TFT1.2@6221.28,5546.87 6221.28,5434.21 6242.27,5413.23 6307.27,5413.23 6395.23,5501.19 R37.2@6395.23,5548.23
$1N15366: R3.2 R23.1 U8.1 | length 141.7
  Bottom Layer w13.8: R23.1@6064.32,4666.18 R3.2@6142.27,4666.19 6203.12,4666.18 U8.1@6205.17,4668.23
$1N17243: BT1.1 BT1.2 BT1.3 R41.1 | length 3325.7
  Top Layer w8: v1(5577.27,4893.23) 5577.27,5183.23 5787.27,5393.23 5787.27,5688.23 5872.27,5773.23 7722.27,5773.23 7781.87,5832.83 7929.94,5832.83 BT1.3@7937.94,5824.83 ; BT1.3@7927.94,5824.83 BT1.3@7937.94,5824.83 ; BT1.1@8124.79,5824.83 BT1.2@8026.37,5824.83 BT1.3@7937.94,5824.83
  Bottom Layer w8: v1(5577.27,4893.23) R41.1@5610.23,4893.23
$1N17767: C39.2 U16.3 | length 65.2
  Top Layer w8: U16.3@4336.76,4961.03 4398.01,4961.03 C39.2@4400.81,4958.23
$1N17771: R42.2 U16.4 | length 75.4
  Top Layer w8: U16.4@4336.76,4986.62 4388.62,4986.62 R42.2@4405.23,5003.23
$1N17778: C38.2 R42.1 | length 40.2
  Top Layer w8: C38.2@4438.73,5043.23 4439.31,5042.65 R42.1@4439.31,5003.23
$1N17783: C39.1 C63.2 R43.2 | length 88
  Top Layer w8: C39.1@4443.73,4958.23 C63.2@4443.73,4913.23 4478.39,4913.23 R43.2@4484.31,4907.31
$1N22623: C40.1 U16.2 | length 76.2
  Top Layer w8: U16.2@4336.76,4935.44 4376.52,4935.44 C40.1@4402.27,4909.69
$1N22693: R44.2 U16.1 | length 67.7
  Top Layer w8: U16.1@4336.76,4909.84 4339.31,4907.29 R44.2@4339.31,4843.23
$1N22964: U16.5 U19.1 | length 251.2
  Top Layer w8: U19.1@4067.66,4807.44 4067.66,4938.62 4115.66,4986.62 U16.5@4167.78,4986.62
$1N22969: U16.8 U19.2 | length 146.3
  Top Layer w8: U19.2@4116.87,4807.44 4116.87,4897.83 4128.88,4909.84 U16.8@4167.78,4909.84
$1N23523: R45.2 U17.4 | length 66.2
  Top Layer w8: R45.2@8052.27,5131.19 8058.88,5124.58 U17.4@8058.88,5067.72
$1N23525: C43.2 R45.1 | length 40.2
  Top Layer w8: C43.2@8012.27,5164.69 8051.69,5164.69 R45.1@8052.27,5165.27
$1N23526: C44.2 U17.3 | length 166.4
  Top Layer w8: C44.2@8058.73,5213.23 8072.27,5213.23 8087.27,5198.23 8087.27,5070.52 U17.3@8084.47,5067.72
$1N23528: C45.1 U17.2 | length 77.4
  Top Layer w8: U17.2@8110.06,5067.72 8110.06,5101.02 8133.73,5124.69 C45.1@8133.73,5135.31
$1N23530: R47.2 U17.1 | length 56.4
  Top Layer w8: U17.1@8135.66,5067.72 8185.74,5067.72 R47.2@8190.23,5063.23
$1N23542: U17.5 U20.1 | length 109.1
  Top Layer w8: U17.5@8058.88,4898.74 8058.88,4856.62 8077.66,4837.83 U20.1@8077.66,4797.44
$1N23545: U17.8 U20.2 | length 104.9
  Top Layer w8: U20.2@8126.87,4797.44 8126.87,4842.83 8135.66,4851.62 U17.8@8135.66,4898.74
$1N24380: C4.2 U1.2 | length 57.5
  Bottom Layer w8: C4.2@6259.35,6221.77 6261.47,6219.65 U1.2@6261.47,6165.19
$1N24407: L1.1 U1.22 | length 144.1
  Bottom Layer w8: L1.1@6368.92,5873.23 6371.67,5875.98 U1.22@6371.67,5968.39
  Bottom Layer w40: 6382.27,5908.23 6388.92,5901.58 L1.1@6388.92,5863.23
$1N27373: SW21.3
$1N36224: Q1.1 R48.2 | length 39
  Top Layer w8: R48.2@6401.68,5381.78 Q1.1@6401.68,5420.83
$1N52523: C44.1 C64.2 R46.2 | length 94.2
  Top Layer w8: C64.2@7970.81,5166.15 7970.81,5211.73 R46.2@7969.31,5213.23 C44.1@8015.81,5213.23
ADC1: SW13.2 U6.7 | length 1340.8
  Bottom Layer w8: SW13.2@4828.41,5046.31 4874.19,5046.31 5152.27,4768.23 5332.27,4768.23 5388.17,4712.33 5835.97,4712.33 5940.14,4816.51 U6.7@5940.14,4864.07
ADC2: SW13.5 U6.6 | length 923.4
  Bottom Layer w8: SW13.5@5172.1,4702.61 5217.72,4748.23 5322.27,4748.23 5373.17,4697.33 5841.37,4697.33 5955.89,4811.85 U6.6@5955.89,4864.07
ADC3: SW17.2 U6.13 | length 2658.6
  Top Layer w8: v1(5632.27,4828.23) 5632.27,5083.23 5782.27,5233.23 5837.27,5233.23 5927.27,5323.23 6462.27,5323.23 6512.27,5373.23 7007.27,5373.23 7187.27,5193.23 7337.27,5193.23 7435.82,5291.78 SW17.2@7435.82,5390.01
  Bottom Layer w8: v1(5632.27,4828.23) 5662.27,4798.23 5802.47,4798.23 5845.65,4841.41 U6.13@5845.65,4864.07
ADC4: SW17.5 U6.14 | length 2332
  Top Layer w8: v1(5682.27,4833.23) 5657.27,4858.23 5657.27,5083.23 5792.27,5218.23 5852.27,5218.23 5937.27,5303.23 6472.27,5303.23 6522.27,5353.23 6997.27,5353.23 7162.27,5188.23 7162.27,5069.4 7139.18,5046.32 SW17.5@7092.12,5046.32
  Bottom Layer w8: v1(5682.27,4833.23) 5702.27,4813.23 5797.67,4813.23 5829.91,4845.47 U6.14@5829.91,4864.07
ALDO1: C2.2 C55.2 C58.2 C60.2 C61.2 C62.2 U1.18 U13.5 U13.8 U14.5 U14.8 | length 7402.7
  Top Layer w8: v1(3722.74,4698.23) U14.8@3722.74,4743.54 ; U13.8@8471.8,4837.91 8471.8,4867.76 8482.27,4878.23 v1(8527.27,4878.23) ; U13.5@8482.13,4768.54 8516.95,4768.54 8527.27,4758.23 C58.2@8552.27,4758.23 ; v1(8552.27,4718.22) C58.2@8552.27,4756.77
  Top Layer w10: v1(3617.27,4858.23) C61.2@3617.27,4824.69 C55.2@3657.27,4824.69 3675.81,4824.69 3687.58,4812.91 U14.5@3712.41,4812.91
  Top Layer w20: v1(8552.27,4718.22) 8553.72,4718.22 C62.2@8592.27,4756.77 C58.2@8552.27,4756.77
  Inner1 w40: v1(3617.27,4858.23) 3617.27,4897.67 v1(3627.82,4908.23) 3642.82,4923.23 4127.27,4923.23 5009.26,5805.22 6308.01,5805.22 6417.27,5914.48 6417.27,5983.23 6467.74,6033.7 v1(6491.26,6033.7) 6611.8,6033.7 6857.27,5788.23 7562.27,5788.23 7786.54,5563.95 7786.54,5413.95 7927.27,5273.23 7927.27,4883.23 8092.28,4718.22 v1(8522.27,4718.23)
  Bottom Layer w8: v1(3617.27,4858.23) 3617.27,4793.23 3712.27,4698.23 v1(3722.74,4698.23) ; U1.18@6414.97,6027.39 6484.95,6027.39 v1(6491.26,6033.7) ; v1(6487.27,6068.23) 6491.28,6064.22 v1(6491.26,6033.7) ; C60.2@6525.81,6043.23 6535.81,6053.23 C2.2@6535.81,6078.23 ; v1(8522.27,4718.23) 8527.27,4723.23 v1(8527.27,4878.23)
  Bottom Layer w20: v1(6487.27,6068.23) v1(6511.26,6068.23) 6525.81,6068.23 C2.2@6535.81,6078.23 ; v1(8522.27,4718.23) v1(8552.27,4718.22)
  other v1: 3612.27,4888.23
ALDO2: C54.2 C56.2 SW13.1 SW13.6 SW17.3 SW17.4 U1.19 | length 4444.5
  Inner1 w40: SW13.6@5270.54,4702.61 5184.91,4788.23 5107.27,4788.23 4927.27,4968.23 4927.27,5045.88 SW13.1@4828.41,5144.74 4828.41,5399.37 5132.27,5703.23 6319.47,5703.23 6500.81,5884.57 ; v1@6502.26,5987.7 v1(6502.26,5963.23) 6502.26,5886.02 6500.81,5884.57 ; SW17.3@7337.39,5390.01 7337.4,5263.36 7218.78,5144.74 SW17.4@7092.12,5144.73 7092.12,5363.38 6787.27,5668.23 6717.15,5668.23 6500.81,5884.57
  Bottom Layer w8: U1.19@6414.97,6011.69 6478.81,6011.69 v1(6500.91,5989.59)
  other v1: 6533.37,5941.5
ALDO3: U1.16
ALDO4: U1.15
BAT: U1.33 U18.1 | length 312.2
  Bottom Layer w8: U18.1@5966.87,5937.44 5966.87,5977.83 5987.27,5998.23 6132.27,5998.23 6161.43,6027.39 U1.33@6218.17,6027.39
EC+: SW15.B U6.51 | length 589.4
  Bottom Layer w8: U6.51@6066.42,4974.61 6148.65,4974.61 6207.27,5033.23 6594.16,5033.23 6605.16,5044.23 SW15.B@6605.16,5066.03
EC-: SW15.A U6.52 | length 584.3
  Bottom Layer w8: U6.52@6066.42,4958.86 6152.9,4958.86 6212.27,5018.23 6554.54,5018.23 SW15.A@6605.16,4967.61
ESP_EN: C30.2 R26.1 U6.4 | length 192.8
  Bottom Layer w8: R26.1@5922.27,4720.27 5959.93,4720.27 C30.2@5960.81,4721.15 5960.81,4776.77 5987.39,4803.35 U6.4@5987.39,4864.07
GND: C1.1 C2.1 C3.1 C4.1 C5.1 C6.1 C7.1 C8.1 C9.1 C10.1 C12.1 C18.2 C26.1 C27.1 C28.1 C29.1 C30.1 C31.1 C32.1 C33.1 C34.1 C35.1 C37.1 C38.1 C40.2 C41.1 C42.1 C43.1 C45.2 C46.1 C47.1 C53.1 C54.1 C55.1 C56.1 C58.1 C60.1 C61.1 C62.1 C63.1 C64.1 H1.3 Q1.2 R1.2 R3.1 R4.1 SW13.3 SW13.4 SW13.7 SW13.8 SW13.9 SW13.10 SW14.1 SW15.C SW17.1 SW17.6 SW17.7 SW17.8 SW17.9 SW17.10 TFT1.1 TFT1.5 TFT1.6 TFT1.12 U1.3 U1.41 U6.57 U13.6 U13.7 U13.11 U14.6 U14.7 U14.11 U15.2 U15.4 U16.7 U17.7 U18.2 U19.3 U19.4 U20.3 U20.4 USB2.0 USB2.A1 USB2.A12 | length 16075.5
  Top Layer w8: v1(3617.27,4753.23) C61.1@3617.27,4781.77 C55.1@3657.27,4781.77 ; U14.7@3712.41,4773.54 3665.49,4773.54 C55.1@3657.27,4781.77 ; U14.6@3712.41,4793.23 3682.27,4793.23 3670.81,4781.77 C55.1@3657.27,4781.77 ; U14.11@3781.8,4743.54 3781.8,4713.7 v1(3792.27,4703.23) ; U19.4@3971.2,4709.01 v1(4105.26,4709.01) U19.3@4213.33,4709.01 ; 4222.27,4935.03 4222.27,4848.23 4213.33,4839.29 U19.3@4213.33,4709.01 ; C47.1@4273.73,5043.23 C38.1@4395.81,5043.23 ; C46.1@4273.73,5083.23 4293.73,5103.23 4673.07,5103.23 SW13.3@4828.41,4947.89 4942.61,4947.89 5073.68,4816.82 SW13.4@5073.69,4702.61 ; C63.1@4443.73,4870.31 4440.19,4866.77 C40.2@4402.27,4866.77 v1(4402.27,4788.23) 4323.05,4709.01 U19.3@4213.33,4709.01 ; C34.1@5797.27,5086.77 C35.1@5837.27,5086.77 5877.27,5086.77 5892.89,5071.14 v2(5892.89,5037.6) ; C26.1@5843.73,4973.23 5867.27,4949.69 C33.1@5867.27,4909.69 5867.89,4910.31 C29.1@6001.54,4910.31 6010.81,4919.57 C32.1@6010.81,4953.23 C37.1@6010.81,4993.23 ; TFT1.12@5945.69,5546.87 5945.69,5611.65 5962.27,5628.23 v1(6037.83,5628.23) 6090.66,5628.23 6110.66,5608.23 ; v2(5971.63,4998.23) 6005.8,4998.23 C37.1@6010.81,4993.23 ; SW14.1@5979.16,5228.23 5979.16,5143.12 5977.27,5141.23 5977.27,5133.23 6010.81,5099.69 C31.1@6010.81,5053.23 C37.1@6010.81,4993.23 ; TFT1.6@6111.05,5546.87 6111.05,5607.84 6110.66,5608.23 ; TFT1.5@6138.61,5546.87 6140.34,5548.6 6140.34,5608.23 ; v1(6207.27,4973.23) 6207.27,4878.23 v1(6282.27,4803.23) ; v1(6252.27,5463.23) 6248.84,5466.65 TFT1.1@6248.84,5546.87 6248.84,5568.87 6250.27,5570.3 6250.27,5618.23 6240.27,5628.23 v1(6181.41,5628.23) 6149.02,5628.23 6140.34,5619.54 6140.34,5608.23 ; v1(6303.73,6306.67) 6311.57,6298.83 v1(6311.57,6109.96) ; v1(6452.27,5460.83) 6452.27,5421.41 Q1.2@6452.85,5420.83 ; SW17.1@7534.24,5390.01 7534.25,5206.25 7652.27,5088.23 v1(8012.27,5088.23) ; C64.1@7970.81,5123.23 8010.81,5123.23 C43.1@8012.27,5121.77 v1(8012.27,5088.23) ; C45.2@8133.73,5178.23 v1(8177.27,5178.23) ; v1(8272.27,4678.23) 8251.48,4699.01 U20.3@8223.33,4699.01 U20.4@7981.2,4699.01 7962.27,4717.95 7962.27,5038.23 v1(8012.27,5088.23) ; U13.11@8412.74,4837.91 v1(8412.74,4878.23) ; U13.6@8482.13,4788.22 8507.26,4788.22 8517.27,4798.23 ; U13.7@8482.13,4807.91 8507.58,4807.91 8517.27,4798.23 ; v1(8592.27,4843.23) C62.1@8592.27,4799.69 8590.81,4798.23 8517.27,4798.23 ; 6110.66,5608.23 6140.34,5608.23
  Top Layer w10: U20.3@8223.33,4699.01 8227.27,4702.95 C42.1@8227.27,4951.77
  Top Layer w20: U16.7@4167.78,4935.03 4222.27,4935.03 4239.07,4935.03 4273.73,4969.69 C47.1@4273.73,5043.23 C46.1@4273.73,5083.23 ; U17.7@8110.06,4898.74 8110.16,4898.84 8110.16,4938.59 8124.79,4953.23 8215.81,4953.23 8219.04,4950 8220.81,4951.77 C42.1@8227.27,4951.77
  Inner2 w8: v1(3792.27,4703.23) 4052.27,4703.23 v1(4057.27,4708.23) ; SW13.4@5073.69,4702.61 5073.68,4692.61 5128.06,4638.23 5572.26,4638.23 5697.55,4763.52 5817.56,4763.52 5892.89,4838.85 v2(5892.89,4958.86) ; v1(5952.27,6043.23) 6002.61,6043.23 v1(6192.27,5853.57) 6274.15,5853.57 6277.27,5850.45 ; v1(5962.27,4648.23) 6082.27,4768.23 v1(6082.27,4813.23) 6082.27,4848.24 v2(5971.63,4958.87) ; v2(5971.63,5037.6) 6112.27,5178.24 6112.27,5328.23 6247.27,5463.23 v1(6252.27,5463.23) ; v1(6273.98,6025.73) 6277.27,6022.44 6277.27,5850.45 ; v1(6351.77,6109.96) 6455.04,6213.23 v1(6523.73,6213.23) ; SW15.C@6605.16,5164.46 6637.27,5196.56 6637.27,5328.23 6504.67,5460.83 v1(6452.27,5460.83) 6449.87,5463.23 v1(6252.27,5463.23) ; v1(6252.27,5463.23) 6252.27,5803.23 6297.27,5848.23 6279.49,5848.23 6277.27,5850.45
  Bottom Layer w8: v1(3617.27,4753.23) 3617.27,4713.23 3662.27,4668.23 3757.27,4668.23 v1(3792.27,4703.23) ; U18.2@5917.66,5937.44 5917.27,5937.84 5917.27,6008.23 v1(5952.27,6043.23) C5.1@6025.81,6043.23 C1.1@6025.81,6083.23 ; C30.1@5960.81,4678.23 5962.27,4676.77 v1(5962.27,4648.23) ; USB2.A1@5971.28,6403.18 5954.85,6419.61 USB2.0@5892.54,6419.61 USB2.0@5892.54,6584.97 USB2.0@6301.99,6584.97 USB2.0@6301.99,6419.61 ; v1(6082.27,4813.23) 6071.38,4802.34 R4.1@6071.38,4769.06 ; R3.1@6142.27,4700.27 6140.17,4700.27 R4.1@6071.38,4769.06 ; R1.2@6142.27,5853.57 v1(6192.27,5853.57) ; v1(6207.27,4973.23) 6240.34,4973.23 U15.2@6247.74,4980.63 ; USB2.A12@6223.25,6403.18 6239.68,6419.61 USB2.0@6301.99,6419.61 ; C28.1@6238.73,5538.23 6238.73,5476.77 v1(6252.27,5463.23) ; U1.3@6277.17,6165.19 6277.17,6188.69 6302.27,6213.78 C4.1@6302.27,6221.77 ; C10.1@6303.73,6268.23 v1(6303.73,6306.67) 6303.73,6417.87 USB2.0@6301.99,6419.61 ; C18.2@6367.27,4936.77 6336.33,4905.83 U15.4@6306.8,4905.83 6306.8,4841.3 C3.1@6303.73,4838.23 6303.73,4824.69 v1(6282.27,4803.23) 6277.27,4808.23 v1(6212.27,4808.23) 6172.27,4808.23 6133.1,4769.06 v1(6110.46,4769.06) R4.1@6071.38,4769.06 ; C6.1@6404.71,5778.23 C8.1@6404.71,5723.23 6404.71,5674.33 C9.1@6405.81,5673.23 ; C27.1@6563.73,5673.23 6567.27,5676.77 6567.27,5725.79 C7.1@6569.83,5723.23 ; SW15.C@6605.16,5164.46 v1(6708.45,5267.74) 6923.93,5483.23 7441.02,5483.23 SW17.1@7534.24,5390.01 7534.25,5215.21 7266.93,4947.89 SW17.6@7092.12,4947.88 ; v1(8012.27,5088.23) 8012.27,5143.23 8047.27,5178.23 v1(8177.27,5178.23) ; v1(8272.27,4678.23) 8282.27,4668.23 8562.27,4668.23 8592.27,4698.23 v1(8592.27,4843.23) 8592.27,4863.23 8552.27,4903.23 8437.74,4903.23 v1(8412.74,4878.23)
  Bottom Layer w20: C53.1@6573.73,6113.23 6578.73,6108.23 C2.1@6578.73,6078.23 6578.73,6053.23 C60.1@6568.73,6043.23 C56.1@6568.73,6003.23 6578.73,5993.23 C54.1@6578.73,5968.23
  other v1: 3712.27,4643.23 6667.27,4644.41 3597.27,4653.23 3897.27,4653.23 8592.27,4653.23 7582.27,4668.23 6002.27,4676.15 6667.27,4676.15 6792.27,4678.23 6975.24,4678.23 7102.27,4678.23 7312.27,4678.23 8617.27,4683.23 7772.27,4688.23 4747.27,4693.23 4372.27,4698.23 4468.55,4698.23 4577.27,4698.23 3652.27,4703.23 3592.27,4708.23 6097.27,4708.23 7877.27,4708.23 6002.27,4713.23 6077.27,4728.23 6667.27,4728.23 6912.27,4728.23 3824.14,4730.73 3859.6,4730.73 6142.27,4738.23 5997.27,4748.23 6797.27,4748.23 4307.27,4758.23 5471.7,4759.43 3867.27,4763.23 7752.27,4763.23 7072.27,4768.23 7502.27,4768.23 7827.27,4773.23 4667.27,4778.23 6667.27,4778.23 4452.27,4787.94 4527.27,4803.23 6362.27,4803.23 6502.27,4808.23 6582.27,4808.23 4202.27,4813.23 6122.27,4813.23 6157.27,4813.23 6412.27,4813.23 6462.21,4813.23 6627.27,4813.23 7767.27,4828.23 5577.27,4833.23 6187.27,4838.23 6677.27,4853.23 8367.27,4853.23 7327.27,4858.23 6192.27,4878.23 6367.27,4878.77 6637.27,4888.23 8627.27,4888.23 6412.27,4898.23 8377.27,4908.23 4640.58,4916.61 8497.27,4918.23 7547.27,4923.23 6692.27,4938.23 4597.27,4953.23 4683.06,4953.23 8482.27,4953.23 8549.41,4953.23 8597.27,4953.23 6467.27,4983.23 7422.27,5008.23 7292.27,5023.23 3608.76,5033.23 3677.27,5033.23 6497.27,5071.65 4507.27,5078.23 6412.27,5077.71 4452.27,5083.23 7347.23,5095.53 6497.27,5118.23 3637.27,5128.23 3720.34,5128.23 3807.27,5128.23 6437.27,5128.23 6551.28,5128.23 3892.27,5133.23 6372.27,5139.4 4622.27,5143.23 6708.45,5146.91 6324.17,5149.42 4572.27,5158.23 4682.19,5158.23 6457.27,5173.23 6359.17,5184.4 6708.45,5211.13 3807.27,5228.23 3907.27,5238.23 6402.27,5238.23 3626.06,5243.23 3722.27,5243.23 4057.27,5318.23 3627.27,5343.23 3772.27,5353.23 5442.27,5353.23 5237.27,5358.23 3917.27,5403.23 5109.11,5416.39 6677.27,5423.23 6817.27,5423.23 6911.02,5423.23 6627.27,5433.23 6737.27,5433.23 6572.27,5453.23 6832.27,5488.23 6306.84,5517.16 6562.27,5528.23 3627.27,5533.23 3907.27,5543.23 6792.27,5543.23 7182.27,5568.23 7277.27,5568.23 7378.48,5568.23 6572.27,5588.23 3902.27,5623.23 6097.27,5633.23 6277.27,5633.23 3872.27,5678.23 3642.27,5683.23 3767.27,5698.23 8197.27,5708.23 8207.11,5873.07 3856.99,5991.17 6311.57,6025.73 6352.23,6027.47 4282.27,6053.23 6273.98,6066.79 6311.57,6066.79 6352.23,6066.79 4392.27,6068.23 3917.27,6078.23 7982.27,6078.23 7217.27,6098.23 4707.27,6103.23 6272.27,6108.23 3992.27,6133.23 7362.27,6143.23 4957.27,6148.23 7082.27,6148.23 7137.27,6158.23 5287.27,6168.23 4632.27,6178.23 6487.27,6183.23 5087.27,6193.23 5817.27,6193.23 4037.27,6198.23 4817.27,6203.23 7277.27,6203.23 7862.27,6203.23 6632.27,6208.23 6697.27,6208.23 4168.16,6229.09 5582.27,6233.23 6597.27,6233.23 7132.27,6233.23 6422.27,6243.23 4842.27,6263.23 5697.27,6293.23 7352.27,6298.23 7247.27,6323.23 4422.27,6333.23 6392.27,6373.23 6567.27,6373.23 7812.27,6373.23 6489.61,6375 5572.27,6383.23 5647.27,6398.23 5717.27,6398.23 5792.27,6398.23 6442.27,6408.23 6489.61,6443.23 6392.27,6443.9 5692.27,6448.23 5747.27,6448.23 5807.27,6448.23
  other v2: 5932.27,4958.87 5892.91,4998.25 5932.26,4998.23 5932.26,5037.6
GPIO0: R43.1 U6.5 | length 1722.5
  Top Layer w8: R43.1@4484.31,4873.23 4712.27,4873.23 4942.27,4643.23 5833.46,4643.23 v1(5877.27,4687.04)
  Bottom Layer w8: v1(5877.27,4687.04) 5877.27,4713.43 5971.64,4807.8 U6.5@5971.64,4864.07
GPIO3: SW1.2 SW2.2 SW3.2 SW4.2 U6.8 | length 3448.9
  Top Layer w8: SW3.2@3931.87,5873.06 4168.16,5873.06 ; SW4.2@4168.16,6109.25 4168.16,5873.06 ; v1(4247.27,5638.23) 4245.91,5636.87 SW1.2@4168.16,5636.87 4168.16,5873.06 ; SW2.2@4404.35,5873.06 4168.16,5873.06
  Bottom Layer w8: v1(4247.27,5638.23) 4262.27,5638.23 4282.27,5658.23 4752.47,5658.23 4850.95,5559.75 4850.95,5216.55 4887.27,5180.23 4887.27,5065.45 5164.49,4788.23 5337.27,4788.23 5398.17,4727.33 5830.97,4727.33 5831.07,4727.23 ; U6.8@5924.39,4864.07 5924.39,4820.76 5922.65,4819.02 5922.65,4818.81 5833.07,4729.23 ; 5831.07,4727.23 5832.87,4729.23 5833.07,4729.23 ; 5831.07,4727.23 5833.07,4729.23
GPIO4: SW2.1 SW7.1 SW12.1 SW13.a SW13.c SW17.a SW17.c U6.9 | length 7109.2
  Top Layer w8: SW2.1@4640.57,5873.06 4640.57,5684.93 v1(4642.27,5683.23) 4642.27,5943.23 4977.27,6278.23 5247.27,6278.23 5392.27,6423.23 5607.27,6423.23 5662.27,6478.23 6537.27,6478.23 6602.27,6413.23 6831.49,6413.23 6897.27,6347.45 6897.27,5978.56 SW12.1@7002.77,5873.06 SW7.1@7435.85,5873.06
  Bottom Layer w8: v1(4642.27,5683.23) 4747.27,5683.23 4962.27,5468.23 4962.27,5332.43 5020.36,5274.34 SW13.c@5035.06,5274.34 ; SW13.c@5027.14,5266.84 5027.56,5266.84 SW13.c@5035.06,5274.34 ; U6.9@5908.65,4864.07 5908.65,4824.61 5827.27,4743.23 5827.07,4743.23 5825.17,4741.33 5546.72,4741.33 5480.32,4807.72 5480.32,4875.17 5432.27,4923.23 5432.27,5098.23 5310.65,5219.85 SW13.a@5310.65,5274.34 5309.82,5273.51 5035.9,5273.51 SW13.c@5035.06,5274.34 ; v1(7372.27,5873.23) 7437.27,5873.23 7732.27,5578.23 7732.27,5251.78 SW17.c@7663.85,5183.36 SW17.a@7663.85,4907.77
GPIO5: SW13.b SW13.d SW21.2 SW23.1 SW23.2 SW24.3 SW24.4 U6.10 | length 4336.1
  Top Layer w8: v1(4452.27,5798.23) 4457.27,5798.23 4512.27,5853.23 4512.27,6306.55 SW21.2@4492.96,6325.86
  Bottom Layer w8: SW24.4@4103.19,4770.75 SW24.3@4103.19,5006.97 4002.27,5107.89 4002.27,5752.44 SW23.1@4050.05,5800.23 SW23.2@4286.27,5800.23 4450.27,5800.23 v1(4452.27,5798.23) 4545.26,5705.24 4750.26,5705.24 5004,5451.5 SW13.d@5035.06,5451.5 SW13.b@5310.65,5451.5 5394.8,5451.5 5482.27,5364.03 5482.27,5138.23 5452.27,5108.23 5452.27,4933.23 5500.26,4885.24 5500.26,4807.58 5552.51,4755.33 5819.37,4755.33 5892.9,4828.86 U6.10@5892.9,4864.07
GPIO6: U6.11 U14.9 | length 3112.7
  Top Layer w8: U14.9@3742.43,4743.54 3742.43,4713.07 3777.27,4678.23 3857.27,4678.23 3897.27,4718.23 3897.27,4968.23 4142.27,5213.23 4757.27,5213.23 4897.27,5353.23 5117.27,5353.23 5177.27,5293.23 5177.27,5033.23 5277.27,4933.23 5492.27,4933.23 v1(5507.27,4918.23)
  Bottom Layer w8: v1(5507.27,4918.23) 5514.26,4911.24 5514.26,4816.24 5561.17,4769.33 5813.17,4769.33 5877.15,4833.31 U6.11@5877.15,4864.07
